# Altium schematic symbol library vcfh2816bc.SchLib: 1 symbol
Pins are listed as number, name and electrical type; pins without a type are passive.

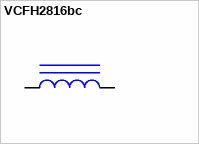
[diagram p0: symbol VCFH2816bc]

## VCFH2816bc
designator L?
Manufacturer: Used in BOM report; SymbolVersion: use current date i.e. 2008-05-20; SymbolCreator: Use a-id; CompType: Used in some BOM reports.  Useful for finding later.; U/M: EA, IN, or GM
footprint PCBComponent_1
pins: 1, 2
